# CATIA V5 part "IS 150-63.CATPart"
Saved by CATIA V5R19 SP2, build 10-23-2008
Part number: IS 150-63
Bounding box of the stored display mesh (mm): x -15.868 to 15.868, y -15.868 to 15.868, z 0 to 177
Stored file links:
  C:\Users\Bora\Desktop\3D Katı model\IS serisi\IS 150\IS 150-63.CATPart
  C:\Program Files\Dassault Systemes\B19\intel_a\reffiles\standard\MetricThickPitch.txt
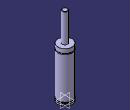
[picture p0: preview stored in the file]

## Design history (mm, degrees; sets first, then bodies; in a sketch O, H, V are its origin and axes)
Body1 (main body)
  Sketch1 on yz-plane, origin (0, 0, 0), H (0, 1, 0), V (0, 0, 1)
    point P3 (6, 176)
    point P5 (6, 176)
    point P7 (16, 102.5)
    point P8 (16, 100.5)
    point P12 (16, 100.5)
    point P13 (16, 102.5)
    line L1 (16, 0) -> (16, 4)
    line L2 (6, 176) -> (6, 112)
    arc A1 centre (5, 176) radius 1 from (6, 176) to (5, 177) ccw
    arc A2 centre (16, 101.5) radius 1 from (16, 102.5) to (16, 100.5) ccw
    line L3 (13.5, 7.5) -> (13.5, 4)
    line L4 (16, 7.5) -> (16, 100.5)
    line L5 (16, 102.5) -> (16, 112)
    line L6 (6, 112) -> (16, 112)
    line L7 (0, 0) -> (16, 0)
    line L8 (13.5, 4) -> (16, 4)
    line L9 (13.5, 7.5) -> (16, 7.5)
    line L10 (5, 177) -> (0, 177)
    point P15 (0, 177)
    horizontal: L6 H, L7 H, L8 H, L9 H
    tangency: L10 A1
    coincidence: P15 V, P3 P5, P7 P13, P8 P12
  Shaft1: profile Sketch1, axis Sketch1.V, angle 360
  Sketch2 on face of Shaft1 from Sketch1.L7, origin (0, 0, 0), H (1, 0, 0), V (0, -1, 0)
    point P1 (0, 0)
  Hole1: placed by Sketch2, at (0, 0, 0) direction (0, 0, 1), diameter 6.647, depth 7, threaded "M8", thread diameter 8, thread depth 7, pitch 1.25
